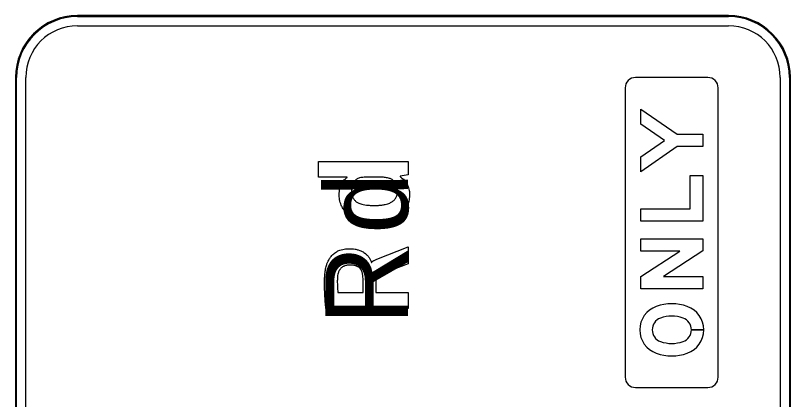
# Model space of a CAD drawing. Extents: x 538465 to 539103, y 1527987 to 1528392.
# Drawn here: x 538772.03 to 538806.4, y 1528374.94 to 1528391.97 of the extents above; entities that cross this region are included whole.
import ezdxf

# ---------------------------------------------------------------- set-up
doc = ezdxf.new("R2010")
doc.units = 0
for name, color, linetype in [('GSBWFill', 7, 'Continuous'), ('GSColorFill', 7, 'Continuous'), ('GSOutline', 7, 'Continuous')]:
    doc.layers.add(name, color=color, linetype=linetype)

msp = doc.modelspace()

# ---------------------------------------------------------------- linework, layer by layer
at = {"layer": 'GSBWFill'}
for p, q in [((538802.557, 1528378.03), (538802.007, 1528378.03)), ((538802.007, 1528378.03), (538802.557, 1528378.03))]:
    msp.add_line(p, q, dxfattribs=at)
for points in [[(538802.509, 1528386.707), (538802.509, 1528386.157), (538801.381, 1528386.157), (538799.759, 1528385.043), (538799.759, 1528385.71), (538800.81, 1528386.432), (538799.759, 1528387.153), (538799.759, 1528387.82), (538801.381, 1528386.707)], [(538801.959, 1528383.393), (538801.959, 1528384.878), (538802.509, 1528384.878), (538802.509, 1528382.843), (538799.759, 1528382.843), (538799.759, 1528383.393)], [(538799.759, 1528379.845), (538799.759, 1528380.395), (538801.491, 1528381.523), (538799.759, 1528381.523), (538799.759, 1528382.073), (538802.509, 1528382.073), (538802.509, 1528381.529), (538800.767, 1528380.395), (538802.509, 1528380.395), (538802.509, 1528379.845)]]:
    msp.add_lwpolyline(points, close=True, dxfattribs=at)
for centre, major_axis, start_param, end_param in [((538801.138, 1528377.137), (-2.049, 0), 4.370195, 5.054583), ((538800.82, 1528378.03), (-1.1, 0), 5.054583, 7.511788), ((538801.457, 1528378.03), (-1.1, 0), 3.141718, 4.370195), ((538800.82, 1528378.03), (-0.55, 0), 5.054583, 7.511788), ((538801.138, 1528377.137), (-1.499, 0), 4.370195, 5.054583), ((538801.457, 1528378.03), (-0.55, 0), 3.141843, 4.370195), ((538801.457, 1528378.03), (-0.55, 0), 1.91299, 3.141593), ((538801.457, 1528378.03), (-1.1, 0), 1.91299, 3.141593), ((538801.138, 1528378.924), (-1.499, 0), 1.228603, 1.91299), ((538801.138, 1528378.924), (-2.049, 0), 1.228603, 1.91299)]:
    msp.add_ellipse(centre, major_axis=major_axis, ratio=0.999995, start_param=start_param, end_param=end_param, dxfattribs=at)
at = {"layer": 'GSColorFill'}
for p, q in [((538803.654, 1528391.972), (538774.779, 1528391.972)), ((538803.654, 1528391.972), (538774.779, 1528391.972)), ((538803.654, 1528391.972), (538774.779, 1528391.972)), ((538774.779, 1528391.927), (538803.654, 1528391.927)), ((538774.779, 1528391.514), (538803.654, 1528391.514)), ((538772.029, 1528389.222), (538772.029, 1528321.847)), ((538772.029, 1528389.222), (538772.029, 1528321.847)), ((538772.029, 1528389.222), (538772.029, 1528321.847)), ((538772.075, 1528321.847), (538772.075, 1528389.222)), ((538772.488, 1528321.847), (538772.488, 1528389.222)), ((538802.738, 1528389.223), (538799.529, 1528389.223)), ((538802.738, 1528389.223), (538799.529, 1528389.223)), ((538805.946, 1528389.222), (538805.946, 1528321.852)), ((538806.359, 1528389.222), (538806.359, 1528321.848)), ((538806.404, 1528321.847), (538806.404, 1528389.222)), ((538806.404, 1528321.852), (538806.404, 1528389.222)), ((538806.404, 1528321.848), (538806.404, 1528389.222)), ((538799.071, 1528388.764), (538799.071, 1528375.931)), ((538799.071, 1528388.764), (538799.071, 1528375.931)), ((538803.196, 1528375.931), (538803.196, 1528388.764)), ((538803.196, 1528375.931), (538803.196, 1528388.764)), ((538802.557, 1528378.03), (538802.007, 1528378.03)), ((538802.007, 1528378.03), (538802.557, 1528378.03)), ((538799.529, 1528375.473), (538802.738, 1528375.473)), ((538799.529, 1528375.473), (538802.738, 1528375.473))]:
    msp.add_line(p, q, dxfattribs=at)
for points in [[(538802.509, 1528386.707), (538802.509, 1528386.157), (538801.381, 1528386.157), (538799.759, 1528385.043), (538799.759, 1528385.71), (538800.81, 1528386.432), (538799.759, 1528387.153), (538799.759, 1528387.82), (538801.381, 1528386.707)], [(538801.959, 1528383.393), (538801.959, 1528384.878), (538802.509, 1528384.878), (538802.509, 1528382.843), (538799.759, 1528382.843), (538799.759, 1528383.393)], [(538799.759, 1528379.845), (538799.759, 1528380.395), (538801.491, 1528381.523), (538799.759, 1528381.523), (538799.759, 1528382.073), (538802.509, 1528382.073), (538802.509, 1528381.529), (538800.767, 1528380.395), (538802.509, 1528380.395), (538802.509, 1528379.845)]]:
    msp.add_lwpolyline(points, close=True, dxfattribs=at)
for centre, radius, start, end in [((538774.779, 1528389.222), 2.75, 90, 180), ((538774.779, 1528389.222), 2.75, 90, 180), ((538774.779, 1528389.222), 2.75, 90, 180), ((538774.779, 1528389.222), 2.704, 90, 180), ((538803.654, 1528389.222), 2.75, 0, 90), ((538803.654, 1528389.222), 2.75, 0, 90), ((538803.654, 1528389.222), 2.75, 0, 90), ((538803.654, 1528389.222), 2.704, 0, 90), ((538774.779, 1528389.222), 2.292, 90, 180), ((538803.654, 1528389.222), 2.292, 0, 90), ((538799.529, 1528388.764), 0.458, 90, 180), ((538799.529, 1528388.764), 0.458, 90, 180), ((538802.738, 1528388.764), 0.458, 0, 90), ((538802.738, 1528388.764), 0.458, 0, 90), ((538799.529, 1528375.931), 0.458, 180, 270), ((538799.529, 1528375.931), 0.458, 180, 270), ((538802.738, 1528375.931), 0.458, 270, 0), ((538802.738, 1528375.931), 0.458, 270, 0)]:
    msp.add_arc(centre, radius, start, end, dxfattribs=at)
for centre, major_axis, start_param, end_param in [((538801.138, 1528377.137), (-2.049, 0), 4.370195, 5.054583), ((538800.82, 1528378.03), (-1.1, 0), 5.054583, 7.511788), ((538801.457, 1528378.03), (-1.1, 0), 3.141718, 4.370195), ((538800.82, 1528378.03), (-0.55, 0), 5.054583, 7.511788), ((538801.138, 1528377.137), (-1.499, 0), 4.370195, 5.054583), ((538801.457, 1528378.03), (-0.55, 0), 3.141843, 4.370195), ((538801.457, 1528378.03), (-0.55, 0), 1.91299, 3.141593), ((538801.457, 1528378.03), (-1.1, 0), 1.91299, 3.141593), ((538801.138, 1528378.924), (-1.499, 0), 1.228603, 1.91299), ((538801.138, 1528378.924), (-2.049, 0), 1.228603, 1.91299)]:
    msp.add_ellipse(centre, major_axis=major_axis, ratio=0.999995, start_param=start_param, end_param=end_param, dxfattribs=at)
at = {"layer": 'GSOutline'}
for points in [[(538802.509, 1528386.707), (538802.509, 1528386.157), (538801.381, 1528386.157), (538799.759, 1528385.043), (538799.759, 1528385.71), (538800.81, 1528386.432), (538799.759, 1528387.153), (538799.759, 1528387.82), (538801.381, 1528386.707)], [(538801.959, 1528383.393), (538801.959, 1528384.878), (538802.509, 1528384.878), (538802.509, 1528382.843), (538799.759, 1528382.843), (538799.759, 1528383.393)], [(538799.759, 1528379.845), (538799.759, 1528380.395), (538801.491, 1528381.523), (538799.759, 1528381.523), (538799.759, 1528382.073), (538802.509, 1528382.073), (538802.509, 1528381.529), (538800.767, 1528380.395), (538802.509, 1528380.395), (538802.509, 1528379.845)]]:
    msp.add_lwpolyline(points, close=True, dxfattribs=at)
for points in [[(538786.744, 1528384.787), (538786.744, 1528384.798), (538785.466, 1528384.798), (538785.466, 1528385.493), (538789.44, 1528385.493), (538789.44, 1528384.903)], [(538788.25, 1528384.798), (538787.534, 1528384.798)], [(538789.44, 1528384.903), (538789.088, 1528384.848), (538789.088, 1528384.823)], [(538788.05, 1528381.158), (538789.44, 1528381.715), (538789.44, 1528380.957)], [(538787.823, 1528381.015), (538787.83, 1528381.015)], [(538789.44, 1528380.957), (538788.164, 1528380.476)], [(538788.014, 1528380.278), (538788.014, 1528379.69), (538789.44, 1528379.69), (538789.44, 1528378.977), (538785.8, 1528378.977)], [(538786.325, 1528379.69), (538787.444, 1528379.69), (538787.444, 1528380.27)]]:
    msp.add_lwpolyline(points, dxfattribs=at)
for centre, major_axis, start_param, end_param in [((538801.138, 1528377.137), (-2.049, 0), 4.370195, 5.054583), ((538800.82, 1528378.03), (-1.1, 0), 5.054583, 7.511788), ((538801.457, 1528378.03), (-1.1, 0), 1.91299, 4.370195), ((538800.82, 1528378.03), (-0.55, 0), 5.054583, 7.511788), ((538801.138, 1528377.137), (-1.499, 0), 4.370195, 5.054583), ((538801.457, 1528378.03), (-0.55, 0), 1.91299, 4.370195), ((538801.138, 1528378.924), (-1.499, 0), 1.228603, 1.91299), ((538801.138, 1528378.924), (-2.049, 0), 1.228603, 1.91299)]:
    msp.add_ellipse(centre, major_axis=major_axis, ratio=0.999995, start_param=start_param, end_param=end_param, dxfattribs=at)
for points in [[(538786.388, 1528384.036), (538786.389, 1528384.073), (538786.391, 1528384.166), (538786.412, 1528384.292), (538786.442, 1528384.395), (538786.466, 1528384.461), (538786.495, 1528384.525), (538786.541, 1528384.6), (538786.611, 1528384.682), (538786.681, 1528384.744), (538786.728, 1528384.776), (538786.744, 1528384.787)], [(538787.534, 1528384.798), (538787.509, 1528384.798), (538787.439, 1528384.796), (538787.338, 1528384.782), (538787.247, 1528384.754), (538787.185, 1528384.725), (538787.138, 1528384.695), (538787.104, 1528384.666), (538787.079, 1528384.64), (538787.056, 1528384.613), (538787.029, 1528384.577), (538786.988, 1528384.503), (538786.953, 1528384.399), (538786.937, 1528384.285), (538786.936, 1528384.219), (538786.936, 1528384.196)], [(538788.981, 1528384.2), (538788.98, 1528384.227), (538788.979, 1528384.267), (538788.972, 1528384.33), (538788.96, 1528384.389), (538788.942, 1528384.444), (538788.924, 1528384.484), (538788.905, 1528384.521), (538788.877, 1528384.565), (538788.838, 1528384.611), (538788.801, 1528384.646), (538788.77, 1528384.67), (538788.736, 1528384.692), (538788.682, 1528384.723), (538788.612, 1528384.75), (538788.538, 1528384.77), (538788.445, 1528384.787), (538788.349, 1528384.797), (538788.275, 1528384.798), (538788.25, 1528384.798)], [(538789.088, 1528384.823), (538789.105, 1528384.811), (538789.155, 1528384.779), (538789.232, 1528384.716), (538789.311, 1528384.632), (538789.366, 1528384.554), (538789.403, 1528384.488), (538789.436, 1528384.418), (538789.469, 1528384.327), (538789.494, 1528384.211), (538789.505, 1528384.111), (538789.506, 1528384.049), (538789.506, 1528384.028)], [(538787.931, 1528382.833), (538787.879, 1528382.834), (538787.729, 1528382.836), (538787.531, 1528382.859), (538787.34, 1528382.897), (538787.162, 1528382.946), (538786.996, 1528383.016), (538786.865, 1528383.095), (538786.779, 1528383.157), (538786.7, 1528383.226), (538786.616, 1528383.319), (538786.555, 1528383.406), (538786.512, 1528383.48), (538786.472, 1528383.559), (538786.433, 1528383.667), (538786.402, 1528383.807), (538786.389, 1528383.932), (538786.388, 1528384.009), (538786.388, 1528384.036)], [(538786.936, 1528384.196), (538786.936, 1528384.178), (538786.937, 1528384.128), (538786.945, 1528384.049), (538786.965, 1528383.961), (538786.991, 1528383.896), (538787.018, 1528383.851), (538787.047, 1528383.809), (538787.087, 1528383.762), (538787.143, 1528383.712), (538787.195, 1528383.678), (538787.252, 1528383.648), (538787.339, 1528383.611), (538787.448, 1528383.582), (538787.594, 1528383.561), (538787.75, 1528383.549), (538787.877, 1528383.547), (538787.942, 1528383.546)], [(538789.506, 1528384.028), (538789.506, 1528384.001), (538789.505, 1528383.924), (538789.491, 1528383.799), (538789.457, 1528383.66), (538789.415, 1528383.553), (538789.372, 1528383.474), (538789.325, 1528383.401), (538789.259, 1528383.314), (538789.169, 1528383.221), (538789.086, 1528383.153), (538788.995, 1528383.091), (538788.859, 1528383.013), (538788.688, 1528382.943), (538788.507, 1528382.896), (538788.318, 1528382.859), (538788.125, 1528382.836), (538787.979, 1528382.834), (538787.931, 1528382.833)], [(538787.942, 1528383.546), (538788.004, 1528383.547), (538788.129, 1528383.55), (538788.283, 1528383.564), (538788.432, 1528383.588), (538788.544, 1528383.619), (538788.636, 1528383.657), (538788.696, 1528383.687), (538788.753, 1528383.723), (538788.813, 1528383.772), (538788.858, 1528383.82), (538788.889, 1528383.862), (538788.919, 1528383.907), (538788.948, 1528383.971), (538788.97, 1528384.056), (538788.98, 1528384.134), (538788.98, 1528384.183), (538788.981, 1528384.2)], [(538785.737, 1528380.191), (538785.74, 1528380.282), (538785.744, 1528380.462), (538785.774, 1528380.683), (538785.82, 1528380.892), (538785.871, 1528381.028), (538785.927, 1528381.135), (538785.957, 1528381.186), (538786, 1528381.251), (538786.061, 1528381.327), (538786.146, 1528381.408), (538786.226, 1528381.466), (538786.295, 1528381.508), (538786.369, 1528381.546), (538786.473, 1528381.585), (538786.61, 1528381.614), (538786.733, 1528381.627), (538786.81, 1528381.628), (538786.837, 1528381.628)], [(538786.837, 1528381.628), (538786.866, 1528381.628), (538786.95, 1528381.626), (538787.086, 1528381.612), (538787.239, 1528381.576), (538787.357, 1528381.531), (538787.444, 1528381.486), (538787.526, 1528381.434), (538787.619, 1528381.354), (538787.715, 1528381.234), (538787.781, 1528381.118), (538787.812, 1528381.042), (538787.823, 1528381.015)], [(538787.83, 1528381.015), (538787.831, 1528381.018), (538787.834, 1528381.025), (538787.839, 1528381.036), (538787.847, 1528381.048), (538787.859, 1528381.062), (538787.878, 1528381.079), (538787.901, 1528381.093), (538787.941, 1528381.111), (538787.989, 1528381.132), (538788.031, 1528381.15), (538788.05, 1528381.158)], [(538786.877, 1528380.902), (538786.85, 1528380.901), (538786.787, 1528380.9), (538786.703, 1528380.888), (538786.637, 1528380.868), (538786.598, 1528380.853), (538786.562, 1528380.835), (538786.52, 1528380.811), (538786.475, 1528380.776), (538786.443, 1528380.742), (538786.42, 1528380.713), (538786.399, 1528380.682), (538786.375, 1528380.639), (538786.348, 1528380.574), (538786.329, 1528380.502), (538786.308, 1528380.374), (538786.305, 1528380.276), (538786.303, 1528380.2)], [(538787.444, 1528380.27), (538787.443, 1528380.294), (538787.443, 1528380.362), (538787.434, 1528380.451), (538787.421, 1528380.524), (538787.409, 1528380.572), (538787.395, 1528380.617), (538787.372, 1528380.667), (538787.349, 1528380.705), (538787.329, 1528380.733), (538787.306, 1528380.759), (538787.275, 1528380.79), (538787.231, 1528380.821), (538787.19, 1528380.843), (538787.155, 1528380.858), (538787.116, 1528380.872), (538787.051, 1528380.889), (538786.967, 1528380.9), (538786.904, 1528380.901), (538786.877, 1528380.902)], [(538788.164, 1528380.476), (538788.151, 1528380.471), (538788.122, 1528380.459), (538788.085, 1528380.439), (538788.06, 1528380.42), (538788.048, 1528380.408), (538788.041, 1528380.4), (538788.035, 1528380.391), (538788.025, 1528380.37), (538788.018, 1528380.34), (538788.014, 1528380.306), (538788.014, 1528380.285), (538788.014, 1528380.278)], [(538785.8, 1528378.977), (538785.788, 1528379.077), (538785.766, 1528379.277), (538785.749, 1528379.581), (538785.739, 1528379.886), (538785.738, 1528380.089), (538785.737, 1528380.191)], [(538786.303, 1528380.2), (538786.303, 1528380.156), (538786.304, 1528380.07), (538786.308, 1528379.942), (538786.315, 1528379.816), (538786.322, 1528379.732), (538786.325, 1528379.69)]]:
    msp.add_open_spline(points, degree=3, dxfattribs=at)

# ---------------------------------------------------------------- texts
at = {"layer": 'GSBWFill'}
for s, p in [('d', (538789.44, 1528382.285)), ('R', (538789.44, 1528378.242))]:
    msp.add_text(s, height=3.667, rotation=90, dxfattribs=at).set_placement(p)
at = {"layer": 'GSColorFill'}
for s, p in [('d', (538789.44, 1528382.285)), ('R', (538789.44, 1528378.242))]:
    msp.add_text(s, height=3.667, rotation=90, dxfattribs=at).set_placement(p)

doc.saveas('drawing.dxf')
